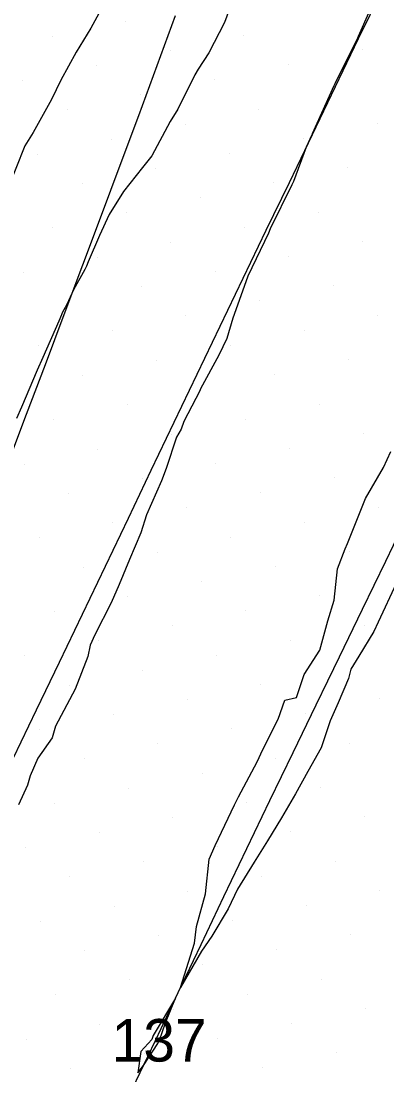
# Model space of a CAD drawing. Extents: x 2354170 to 2357230, y 866100 to 868290.
# Drawn here: x 2355276.5 to 2355293.68, y 866360.82 to 866410.37 of the extents above; entities that cross this region are included whole.
import ezdxf

# ---------------------------------------------------------------- set-up
doc = ezdxf.new("R2010")
doc.units = 0
for name, color, linetype in [('Default', 7, 'Continuous'), ('DTM Contours Minor', 7, 'Continuous'), ('DTM Contours Minor Text', 7, 'Continuous'), ('Exist DTM Breakline', 7, 'Continuous'), ('Exist DTM Scan Elevation Point', 7, 'Continuous')]:
    doc.layers.add(name, color=color, linetype=linetype)

msp = doc.modelspace()

# ---------------------------------------------------------------- linework, layer by layer
at = {"layer": 'Default'}
for points in [[(2355293.312, 866411.847), (2355292.335, 866409.643), (2355292.308, 866409.562), (2355291.234, 866407.422), (2355291.197, 866407.322), (2355290.176, 866405.066), (2355290.167, 866405.045), (2355290.155, 866405.022), (2355289.897, 866404.434), (2355289.294, 866402.831), (2355289.219, 866402.662), (2355288.202, 866400.594), (2355288.13, 866400.4), (2355287.147, 866398.376), (2355287.059, 866398.105), (2355286.452, 866396.405), (2355286.158, 866395.442), (2355285.791, 866394.657), (2355284.936, 866393.08), (2355284.896, 866392.976), (2355284.149, 866391.535), (2355284.025, 866391.184), (2355283.801, 866390.797), (2355283.308, 866389.33), (2355283.094, 866388.747), (2355282.399, 866387.154), (2355282.13, 866386.304), (2355281.595, 866385.05), (2355281.104, 866383.875), (2355280.725, 866383.009), (2355279.966, 866381.516), (2355279.748, 866381.021), (2355279.638, 866380.484), (2355279.036, 866378.962), (2355278.118, 866377.214), (2355277.964, 866376.673), (2355277.283, 866375.709), (2355276.921, 866374.876), (2355276.797, 866374.448), (2355276.385, 866373.525)], [(2355280.347, 866411.068), (2355279.785, 866410.027), (2355279.093, 866408.9), (2355278.375, 866407.586), (2355277.922, 866406.677), (2355277.072, 866405.123), (2355276.678, 866404.503), (2355275.83, 866402.366)], [(2355286.447, 866411.384), (2355286.049, 866410.293), (2355285.327, 866408.88), (2355284.815, 866408.112), (2355284.657, 866407.834), (2355283.871, 866406.223), (2355283.502, 866405.651), (2355282.638, 866404.025), (2355282.205, 866403.489), (2355281.318, 866402.362), (2355280.632, 866401.277), (2355280.178, 866400.285), (2355279.659, 866399.044), (2355279.574, 866398.842), (2355279.499, 866398.682), (2355278.959, 866397.733), (2355278.654, 866397.044), (2355278.436, 866396.654), (2355278.393, 866396.563), (2355278.273, 866396.264), (2355277.518, 866394.55), (2355277.262, 866393.956), (2355276.517, 866392.213), (2355276.284, 866391.681)]]:
    msp.add_lwpolyline(points, dxfattribs=at)
at = {"layer": 'DTM Contours Minor'}
for points in [[(2355294.137, 866383.959), (2355293.278, 866382.106), (2355293.072, 866381.666), (2355292.362, 866380.506), (2355291.997, 866379.9), (2355291.881, 866379.456), (2355291.392, 866378.321), (2355291.022, 866377.471), (2355290.593, 866376.194), (2355289.972, 866375.086), (2355289.39, 866374.032), (2355288.736, 866372.911), (2355288.068, 866371.832), (2355287.453, 866370.815), (2355286.667, 866369.557), (2355286.233, 866368.62), (2355285.463, 866367.346), (2355284.983, 866366.637), (2355283.992, 866364.933), (2355284.641, 866367.021), (2355284.747, 866367.791), (2355285.166, 866369.339), (2355285.334, 866370.97), (2355285.624, 866371.606), (2355286.533, 866373.516), (2355286.707, 866373.887), (2355287.594, 866375.536), (2355287.863, 866376.119), (2355288.579, 866377.541), (2355288.893, 866378.435), (2355289.437, 866378.565), (2355289.799, 866379.639), (2355290.527, 866380.792), (2355290.908, 866382.167), (2355291.202, 866383.14), (2355291.367, 866384.62), (2355291.726, 866385.554), (2355291.832, 866385.798), (2355292.674, 866387.924), (2355293.531, 866389.374), (2355293.872, 866390.129)], [(2355282.997, 866362.446), (2355283.285, 866363.263), (2355283.75, 866364.425), (2355282.705, 866362.674), (2355282.636, 866362.49), (2355282.13, 866361.926), (2355281.981, 866360.923), (2355282.248, 866361.266), (2355282.922, 866362.292), (2355282.997, 866362.446)]]:
    msp.add_lwpolyline(points, dxfattribs=at)
at = {"layer": 'Exist DTM Breakline'}
for points in [[(2355281.733, 866360.182), (2355282.807, 866362.44), (2355283.88, 866364.698), (2355284.954, 866366.955), (2355286.027, 866369.213), (2355287.104, 866371.469), (2355288.192, 866373.72), (2355289.279, 866375.971), (2355290.367, 866378.223), (2355291.454, 866380.474), (2355292.542, 866382.725), (2355293.629, 866384.976), (2355294.717, 866387.227), (2355295.804, 866389.478), (2355296.892, 866391.729), (2355297.979, 866393.98), (2355299.067, 866396.231), (2355300.154, 866398.482), (2355301.242, 866400.733), (2355302.329, 866402.984), (2355303.416, 866405.236), (2355304.501, 866407.488), (2355305.586, 866409.74), (2355306.671, 866411.993)], [(2355268.566, 866359.952), (2355269.653, 866362.203), (2355270.739, 866364.455), (2355271.822, 866366.708), (2355272.905, 866368.961), (2355273.989, 866371.214), (2355275.071, 866373.468), (2355276.152, 866375.722), (2355277.232, 866377.977), (2355278.312, 866380.231), (2355279.392, 866382.486), (2355280.467, 866384.743), (2355281.541, 866387.001), (2355282.616, 866389.258), (2355283.691, 866391.515), (2355284.773, 866393.769), (2355285.855, 866396.023), (2355286.936, 866398.276), (2355288.018, 866400.53), (2355289.102, 866402.783), (2355290.186, 866405.036), (2355291.27, 866407.289), (2355292.354, 866409.541), (2355293.44, 866411.793)], [(2355264.265, 866359.194), (2355265.171, 866361.524), (2355266.077, 866363.853), (2355266.984, 866366.183), (2355267.877, 866368.518), (2355268.77, 866370.854), (2355269.663, 866373.189), (2355270.556, 866375.524), (2355271.442, 866377.861), (2355272.328, 866380.199), (2355273.214, 866382.537), (2355274.1, 866384.874), (2355274.986, 866387.212), (2355275.871, 866389.55), (2355276.756, 866391.888), (2355277.641, 866394.227), (2355278.521, 866396.567), (2355279.4, 866398.907), (2355280.279, 866401.247), (2355281.158, 866403.588), (2355282.024, 866405.933), (2355282.89, 866408.278), (2355283.756, 866410.623)]]:
    msp.add_lwpolyline(points, dxfattribs=at)
at = {"layer": 'Exist DTM Scan Elevation Point'}
for p, q in [((2355281.418, 866410.359), (2355281.418, 866410.359)), ((2355277.954, 866409.654), (2355277.954, 866409.654)), ((2355286.968, 866409.686), (2355286.968, 866409.686)), ((2355283.503, 866408.98), (2355283.503, 866408.98)), ((2355292.517, 866409.012), (2355292.517, 866409.012)), ((2355280.039, 866408.274), (2355280.039, 866408.274)), ((2355289.053, 866408.306), (2355289.053, 866408.306)), ((2355276.574, 866407.569), (2355276.574, 866407.569)), ((2355285.588, 866407.601), (2355285.588, 866407.601)), ((2355282.124, 866406.895), (2355282.124, 866406.895)), ((2355278.659, 866406.189), (2355278.659, 866406.189)), ((2355287.673, 866406.221), (2355287.673, 866406.221)), ((2355284.209, 866405.516), (2355284.209, 866405.516)), ((2355293.222, 866405.547), (2355293.222, 866405.547)), ((2355280.744, 866404.81), (2355280.744, 866404.81)), ((2355289.758, 866404.842), (2355289.758, 866404.842)), ((2355277.28, 866404.104), (2355277.28, 866404.104)), ((2355286.294, 866404.136), (2355286.294, 866404.136)), ((2355282.829, 866403.431), (2355282.829, 866403.431)), ((2355291.843, 866403.462), (2355291.843, 866403.462)), ((2355279.365, 866402.725), (2355279.365, 866402.725)), ((2355288.379, 866402.757), (2355288.379, 866402.757)), ((2355284.914, 866402.051), (2355284.914, 866402.051)), ((2355281.45, 866401.346), (2355281.45, 866401.346)), ((2355290.464, 866401.377), (2355290.464, 866401.377)), ((2355277.985, 866400.64), (2355277.985, 866400.64)), ((2355286.999, 866400.672), (2355286.999, 866400.672)), ((2355283.535, 866399.966), (2355283.535, 866399.966)), ((2355292.549, 866399.998), (2355292.549, 866399.998)), ((2355280.07, 866399.261), (2355280.07, 866399.261)), ((2355289.084, 866399.292), (2355289.084, 866399.292)), ((2355276.606, 866398.555), (2355276.606, 866398.555)), ((2355285.62, 866398.587), (2355285.62, 866398.587)), ((2355282.155, 866397.881), (2355282.155, 866397.881)), ((2355291.169, 866397.913), (2355291.169, 866397.913)), ((2355278.691, 866397.176), (2355278.691, 866397.176)), ((2355287.705, 866397.207), (2355287.705, 866397.207)), ((2355284.24, 866396.502), (2355284.24, 866396.502)), ((2355293.254, 866396.533), (2355293.254, 866396.533)), ((2355280.776, 866395.796), (2355280.776, 866395.796)), ((2355289.79, 866395.828), (2355289.79, 866395.828)), ((2355277.312, 866395.091), (2355277.312, 866395.091)), ((2355286.325, 866395.122), (2355286.325, 866395.122)), ((2355282.861, 866394.417), (2355282.861, 866394.417)), ((2355291.875, 866394.448), (2355291.875, 866394.448)), ((2355279.397, 866393.711), (2355279.397, 866393.711)), ((2355288.41, 866393.743), (2355288.41, 866393.743)), ((2355284.946, 866393.037), (2355284.946, 866393.037)), ((2355281.481, 866392.332), (2355281.481, 866392.332)), ((2355290.495, 866392.363), (2355290.495, 866392.363)), ((2355278.017, 866391.626), (2355278.017, 866391.626)), ((2355287.031, 866391.658), (2355287.031, 866391.658)), ((2355283.566, 866390.952), (2355283.566, 866390.952)), ((2355292.58, 866390.984), (2355292.58, 866390.984)), ((2355280.102, 866390.247), (2355280.102, 866390.247)), ((2355289.116, 866390.278), (2355289.116, 866390.278)), ((2355276.638, 866389.541), (2355276.638, 866389.541)), ((2355285.651, 866389.573), (2355285.651, 866389.573)), ((2355282.187, 866388.867), (2355282.187, 866388.867)), ((2355291.201, 866388.899), (2355291.201, 866388.899)), ((2355278.723, 866388.162), (2355278.723, 866388.162)), ((2355287.736, 866388.193), (2355287.736, 866388.193)), ((2355284.272, 866387.488), (2355284.272, 866387.488)), ((2355293.286, 866387.52), (2355293.286, 866387.52)), ((2355280.808, 866386.782), (2355280.808, 866386.782)), ((2355289.821, 866386.814), (2355289.821, 866386.814)), ((2355277.343, 866386.077), (2355277.343, 866386.077)), ((2355286.357, 866386.108), (2355286.357, 866386.108)), ((2355282.893, 866385.403), (2355282.893, 866385.403)), ((2355291.906, 866385.435), (2355291.906, 866385.435)), ((2355279.428, 866384.697), (2355279.428, 866384.697)), ((2355288.442, 866384.729), (2355288.442, 866384.729)), ((2355284.978, 866384.024), (2355284.978, 866384.024)), ((2355281.513, 866383.318), (2355281.513, 866383.318)), ((2355290.527, 866383.35), (2355290.527, 866383.35)), ((2355278.049, 866382.612), (2355278.049, 866382.612)), ((2355287.063, 866382.644), (2355287.063, 866382.644)), ((2355283.598, 866381.939), (2355283.598, 866381.939)), ((2355292.612, 866381.97), (2355292.612, 866381.97)), ((2355280.134, 866381.233), (2355280.134, 866381.233)), ((2355289.148, 866381.265), (2355289.148, 866381.265)), ((2355276.669, 866380.527), (2355276.669, 866380.527)), ((2355285.683, 866380.559), (2355285.683, 866380.559)), ((2355282.219, 866379.854), (2355282.219, 866379.854)), ((2355291.233, 866379.885), (2355291.233, 866379.885)), ((2355278.754, 866379.148), (2355278.754, 866379.148)), ((2355287.768, 866379.18), (2355287.768, 866379.18)), ((2355284.304, 866378.474), (2355284.304, 866378.474)), ((2355293.318, 866378.506), (2355293.318, 866378.506)), ((2355280.839, 866377.769), (2355280.839, 866377.769)), ((2355289.853, 866377.8), (2355289.853, 866377.8)), ((2355277.375, 866377.063), (2355277.375, 866377.063)), ((2355286.389, 866377.095), (2355286.389, 866377.095)), ((2355282.924, 866376.389), (2355282.924, 866376.389)), ((2355291.938, 866376.421), (2355291.938, 866376.421)), ((2355279.46, 866375.684), (2355279.46, 866375.684)), ((2355288.474, 866375.715), (2355288.474, 866375.715)), ((2355285.009, 866375.01), (2355285.009, 866375.01)), ((2355281.545, 866374.304), (2355281.545, 866374.304)), ((2355290.559, 866374.336), (2355290.559, 866374.336)), ((2355278.08, 866373.599), (2355278.08, 866373.599)), ((2355287.094, 866373.63), (2355287.094, 866373.63)), ((2355283.63, 866372.925), (2355283.63, 866372.925)), ((2355292.644, 866372.956), (2355292.644, 866372.956)), ((2355280.165, 866372.219), (2355280.165, 866372.219)), ((2355289.179, 866372.251), (2355289.179, 866372.251)), ((2355276.701, 866371.514), (2355276.701, 866371.514)), ((2355285.715, 866371.545), (2355285.715, 866371.545)), ((2355282.25, 866370.84), (2355282.25, 866370.84)), ((2355291.264, 866370.871), (2355291.264, 866370.871)), ((2355278.786, 866370.134), (2355278.786, 866370.134)), ((2355287.8, 866370.166), (2355287.8, 866370.166)), ((2355284.335, 866369.46), (2355284.335, 866369.46)), ((2355293.349, 866369.492), (2355293.349, 866369.492)), ((2355280.871, 866368.755), (2355280.871, 866368.755)), ((2355289.885, 866368.786), (2355289.885, 866368.786)), ((2355277.407, 866368.049), (2355277.407, 866368.049)), ((2355286.42, 866368.081), (2355286.42, 866368.081)), ((2355282.956, 866367.375), (2355282.956, 866367.375)), ((2355291.97, 866367.407), (2355291.97, 866367.407)), ((2355279.492, 866366.67), (2355279.492, 866366.67)), ((2355288.505, 866366.701), (2355288.505, 866366.701)), ((2355285.041, 866365.996), (2355285.041, 866365.996)), ((2355281.577, 866365.29), (2355281.577, 866365.29)), ((2355290.59, 866365.322), (2355290.59, 866365.322)), ((2355278.112, 866364.585), (2355278.112, 866364.585)), ((2355287.126, 866364.616), (2355287.126, 866364.616)), ((2355283.662, 866363.911), (2355283.662, 866363.911)), ((2355292.675, 866363.943), (2355292.675, 866363.943)), ((2355280.197, 866363.205), (2355280.197, 866363.205)), ((2355289.211, 866363.237), (2355289.211, 866363.237)), ((2355276.733, 866362.5), (2355276.733, 866362.5)), ((2355285.747, 866362.531), (2355285.747, 866362.531)), ((2355282.282, 866361.826), (2355282.282, 866361.826)), ((2355291.296, 866361.858), (2355291.296, 866361.858)), ((2355278.818, 866361.12), (2355278.818, 866361.12)), ((2355287.831, 866361.152), (2355287.831, 866361.152))]:
    msp.add_line(p, q, dxfattribs=at)

# ---------------------------------------------------------------- texts
at = {"layer": 'DTM Contours Minor Text'}
msp.add_text('137', height=2, dxfattribs=at).set_placement((2355280.753, 866361.446))

doc.saveas('drawing.dxf')
